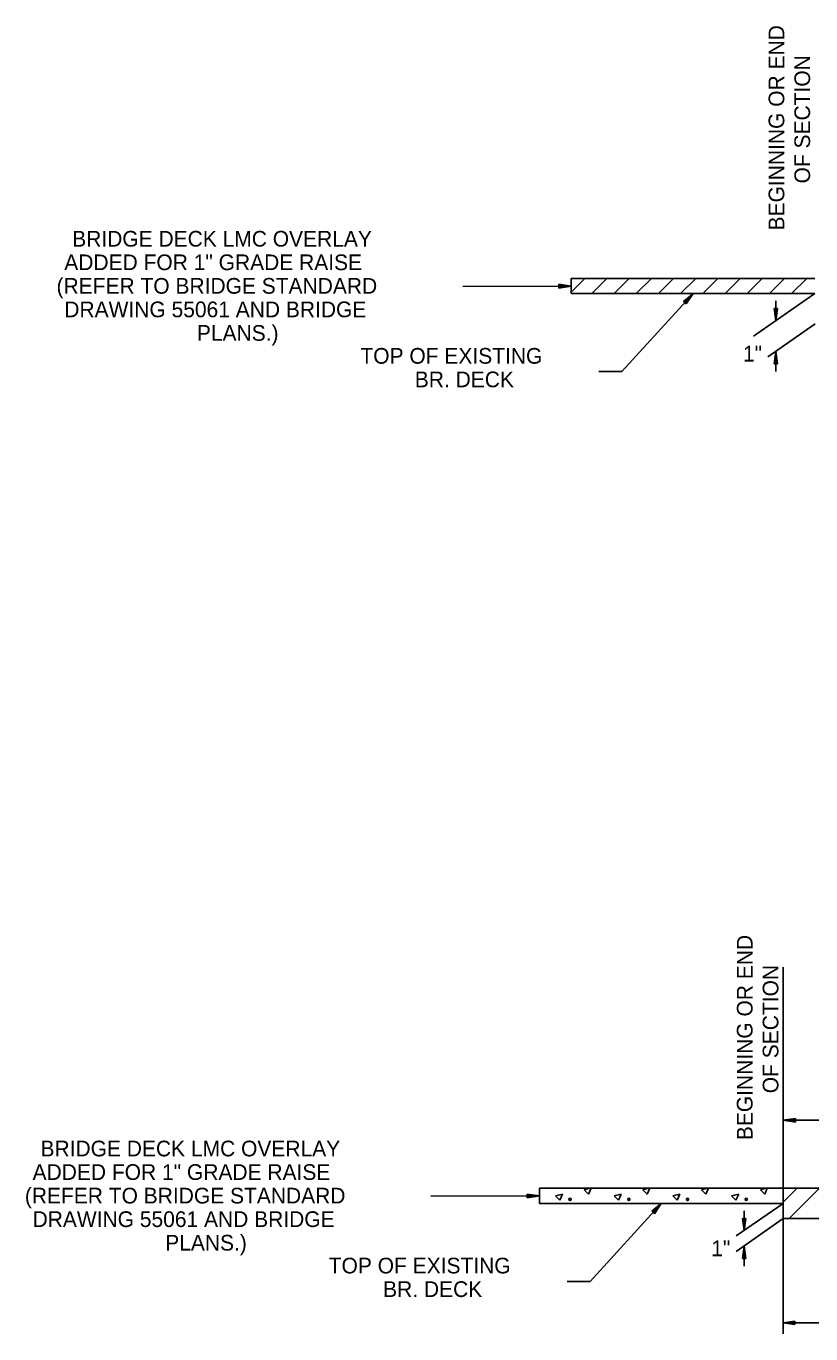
# Model space of a CAD drawing. Extents: x 1929624 to 1935547, y 596315 to 605721.
# Drawn here: x 1931522.3 to 1931822.3, y 602426.5 to 602926.3 of the extents above; entities that cross this region are included whole.
import ezdxf

# ---------------------------------------------------------------- set-up
doc = ezdxf.new("R2010")
doc.units = 0
doc.layers.add('Default', color=7, linetype='Continuous')
doc.layers.add('R_Annotation', color=7, linetype='Continuous')

msp = doc.modelspace()

# ---------------------------------------------------------------- linework, layer by layer
at = {"layer": 'Default'}
for p, q in [((1931689.17, 602826.79), (1931730.62, 602826.95)), ((1931725.91, 602826.22), (1931725.96, 602827.63)), ((1931725.91, 602826.22), (1931730.62, 602826.95)), ((1931725.92, 602827.33), (1931729.03, 602826.88)), ((1931725.96, 602827.63), (1931730.62, 602826.95)), ((1931725.96, 602826.53), (1931727.61, 602826.92)), ((1931725.96, 602826.53), (1931728.22, 602826.83)), ((1931726.01, 602826.84), (1931726.8, 602826.89)), ((1931726.01, 602826.84), (1931726.8, 602826.89)), ((1931726.05, 602827.15), (1931727.61, 602826.92)), ((1931726.05, 602827.15), (1931728.22, 602826.83)), ((1931726.09, 602827.46), (1931729.83, 602826.91)), ((1931726.09, 602826.36), (1931729.83, 602826.91)), ((1931726.09, 602826.36), (1931729.03, 602826.88)), ((1931730.62, 602824.06), (1931823.87, 602824.07)), ((1931750.04, 602794.26), (1931777.25, 602824.07)), ((1931773.59, 602821.1), (1931777.25, 602824.07)), ((1931774.59, 602820.11), (1931773.59, 602821.1)), ((1931773.78, 602820.86), (1931776.22, 602822.84)), ((1931773.8, 602821.08), (1931776.74, 602823.46)), ((1931774.01, 602820.84), (1931775.7, 602822.21)), ((1931774.01, 602820.84), (1931775.23, 602821.83)), ((1931774.21, 602820.6), (1931774.7, 602821.21)), ((1931774.21, 602820.6), (1931774.7, 602821.21)), ((1931774.4, 602820.36), (1931775.7, 602822.21)), ((1931774.4, 602820.36), (1931775.23, 602821.83)), ((1931774.59, 602820.11), (1931777.25, 602824.07)), ((1931774.61, 602820.33), (1931776.74, 602823.46)), ((1931774.61, 602820.33), (1931776.22, 602822.84)), ((1931800.32, 602807.77), (1931823.87, 602824.07)), ((1931808.93, 602813.69), (1931808.93, 602821.27)), ((1931808.27, 602818.35), (1931808.93, 602813.69)), ((1931809.6, 602818.35), (1931808.27, 602818.35)), ((1931808.49, 602818.35), (1931808.93, 602815.25)), ((1931808.49, 602818.35), (1931808.93, 602814.59)), ((1931808.7, 602818.35), (1931808.93, 602816.81)), ((1931808.7, 602818.35), (1931808.93, 602816.14)), ((1931809.6, 602818.35), (1931808.93, 602813.69)), ((1931809.15, 602818.35), (1931808.93, 602816.81)), ((1931809.38, 602818.35), (1931808.93, 602815.25)), ((1931809.6, 602818.35), (1931808.93, 602814.59)), ((1931809.38, 602818.35), (1931808.93, 602816.14)), ((1931808.93, 602818.35), (1931808.93, 602817.69)), ((1931809.15, 602818.35), (1931808.93, 602817.69)), ((1931805.89, 602799.86), (1931823.88, 602812.53)), ((1931808.25, 602797.23), (1931808.91, 602801.9)), ((1931808.48, 602797.23), (1931808.91, 602801.23)), ((1931808.48, 602797.23), (1931808.91, 602800.34)), ((1931808.68, 602797.23), (1931808.91, 602799.67)), ((1931809.58, 602797.23), (1931808.91, 602801.9)), ((1931808.91, 602794.35), (1931808.91, 602801.9)), ((1931809.58, 602797.23), (1931808.91, 602801.23)), ((1931809.36, 602797.23), (1931808.91, 602800.34)), ((1931809.36, 602797.23), (1931808.91, 602799.67)), ((1931750.04, 602794.26), (1931741.27, 602794.26)), ((1931808.25, 602797.23), (1931809.58, 602797.23)), ((1931808.68, 602797.23), (1931808.91, 602798.78)), ((1931809.13, 602797.23), (1931808.91, 602798.78)), ((1931809.13, 602797.23), (1931808.91, 602798.13)), ((1931808.91, 602797.23), (1931808.91, 602798.13)), ((1931811.75, 602482.14), (1931811.75, 602566.66)), ((1931816.41, 602508.8), (1931811.75, 602508.13)), ((1931811.75, 602508.13), (1932223.07, 602508.13)), ((1931816.41, 602507.47), (1931811.75, 602508.13)), ((1931816.41, 602508.58), (1931812.42, 602508.13)), ((1931816.41, 602507.47), (1931812.42, 602508.13)), ((1931816.41, 602508.58), (1931813.31, 602508.13)), ((1931816.41, 602507.69), (1931813.31, 602508.13)), ((1931816.41, 602508.35), (1931814.2, 602508.13)), ((1931816.41, 602507.69), (1931814.2, 602508.13)), ((1931816.41, 602508.35), (1931814.87, 602508.13)), ((1931816.41, 602507.92), (1931814.87, 602508.13)), ((1931816.41, 602508.13), (1931815.75, 602508.13)), ((1931816.41, 602507.92), (1931815.75, 602508.13)), ((1931816.41, 602507.47), (1931816.41, 602508.8)), ((1931713.78, 602478.53), (1931713.83, 602479.94)), ((1931713.79, 602479.64), (1931716.9, 602479.18)), ((1931713.83, 602479.94), (1931718.5, 602479.25)), ((1931713.93, 602479.45), (1931715.48, 602479.22)), ((1931713.93, 602479.45), (1931716.09, 602479.13)), ((1931713.96, 602479.77), (1931717.7, 602479.22)), ((1931677.04, 602479.1), (1931718.5, 602479.25)), ((1931713.78, 602478.53), (1931718.5, 602479.25)), ((1931713.84, 602478.84), (1931715.48, 602479.22)), ((1931713.84, 602478.84), (1931716.09, 602479.13)), ((1931713.89, 602479.14), (1931714.67, 602479.19)), ((1931713.89, 602479.14), (1931714.67, 602479.19)), ((1931713.97, 602478.67), (1931717.7, 602479.22)), ((1931713.97, 602478.67), (1931716.9, 602479.18)), ((1931718.5, 602476.37), (1931811.75, 602476.38)), ((1931737.92, 602446.57), (1931765.12, 602476.37)), ((1931761.46, 602473.4), (1931765.12, 602476.37)), ((1931761.65, 602473.17), (1931764.09, 602475.15)), ((1931761.67, 602473.38), (1931764.61, 602475.76)), ((1931761.88, 602473.14), (1931763.58, 602474.52)), ((1931762.27, 602472.66), (1931763.58, 602474.52)), ((1931762.46, 602472.41), (1931765.12, 602476.37)), ((1931762.49, 602472.64), (1931764.61, 602475.76)), ((1931762.49, 602472.64), (1931764.09, 602475.15)), ((1931793.76, 602463.93), (1931811.75, 602476.38)), ((1931811.75, 602426.51), (1931811.75, 602476.38)), ((1931762.46, 602472.41), (1931761.46, 602473.4)), ((1931761.88, 602473.14), (1931763.1, 602474.13)), ((1931762.08, 602472.9), (1931762.58, 602473.51)), ((1931762.08, 602472.9), (1931762.58, 602473.51)), ((1931762.27, 602472.66), (1931763.1, 602474.13)), ((1931793.76, 602457.93), (1931811.75, 602470.6)), ((1931796.14, 602470.66), (1931796.8, 602465.99)), ((1931797.47, 602470.66), (1931796.14, 602470.66)), ((1931796.37, 602470.66), (1931796.8, 602467.55)), ((1931796.37, 602470.66), (1931796.8, 602466.89)), ((1931796.57, 602470.66), (1931796.8, 602469.11)), ((1931796.57, 602470.66), (1931796.8, 602468.44)), ((1931796.8, 602465.99), (1931796.8, 602473.57)), ((1931797.47, 602470.66), (1931796.8, 602465.99)), ((1931797.02, 602470.66), (1931796.8, 602469.11)), ((1931797.25, 602470.66), (1931796.8, 602467.55)), ((1931797.47, 602470.66), (1931796.8, 602466.89)), ((1931797.25, 602470.66), (1931796.8, 602468.44)), ((1931796.8, 602470.66), (1931796.8, 602469.99)), ((1931797.02, 602470.66), (1931796.8, 602469.99)), ((1931796.12, 602455.31), (1931796.78, 602459.98)), ((1931797.45, 602455.31), (1931796.78, 602459.98)), ((1931796.78, 602452.42), (1931796.78, 602459.98)), ((1931796.12, 602455.31), (1931797.45, 602455.31)), ((1931796.35, 602455.31), (1931796.78, 602459.31)), ((1931796.35, 602455.31), (1931796.78, 602458.41)), ((1931796.55, 602455.31), (1931796.78, 602457.75)), ((1931796.55, 602455.31), (1931796.78, 602456.85)), ((1931797.45, 602455.31), (1931796.78, 602459.31)), ((1931797.23, 602455.31), (1931796.78, 602458.41)), ((1931797.23, 602455.31), (1931796.78, 602457.75)), ((1931797, 602455.31), (1931796.78, 602456.85)), ((1931797, 602455.31), (1931796.78, 602456.2)), ((1931796.78, 602455.31), (1931796.78, 602456.2)), ((1931737.92, 602446.57), (1931729.14, 602446.57)), ((1931816.21, 602431.36), (1931811.75, 602430.71)), ((1932223.07, 602430.71), (1931811.75, 602430.71)), ((1931816.21, 602430.04), (1931811.75, 602430.71)), ((1931816.21, 602431.36), (1931812.42, 602430.71)), ((1931816.21, 602430.26), (1931812.42, 602430.71)), ((1931816.21, 602431.16), (1931813.31, 602430.71)), ((1931816.21, 602430.26), (1931813.31, 602430.71)), ((1931816.21, 602431.16), (1931813.97, 602430.71)), ((1931816.21, 602430.48), (1931813.97, 602430.71)), ((1931816.21, 602430.92), (1931814.87, 602430.71)), ((1931816.21, 602430.48), (1931814.87, 602430.71)), ((1931816.21, 602430.92), (1931815.53, 602430.71)), ((1931816.21, 602430.71), (1931815.53, 602430.71)), ((1931816.21, 602430.04), (1931816.21, 602431.36))]:
    msp.add_line(p, q, dxfattribs=at)
msp.add_lwpolyline([(1931811.75, 602476.38), (1931811.75, 602476.38)], dxfattribs=at)
at = {"layer": 'R_Annotation'}
for p, q in [((1931810.01, 602829.84), (1931730.62, 602829.83)), ((1931730.62, 602829.83), (1931730.62, 602824.06)), ((1931730.62, 602824.61), (1931735.85, 602829.83)), ((1931738.56, 602824.06), (1931744.33, 602829.83)), ((1931747.05, 602824.06), (1931752.82, 602829.83)), ((1931755.54, 602824.06), (1931761.31, 602829.83)), ((1931764.02, 602824.07), (1931769.79, 602829.84)), ((1931772.51, 602824.07), (1931778.28, 602829.84)), ((1931780.99, 602824.07), (1931786.76, 602829.84)), ((1931789.48, 602824.07), (1931795.25, 602829.84)), ((1931797.97, 602824.07), (1931803.74, 602829.84)), ((1931806.45, 602824.07), (1931812.22, 602829.84)), ((1931823.87, 602829.84), (1931810.01, 602829.84)), ((1931814.94, 602824.07), (1931820.7, 602829.84)), ((1931797.88, 602482.14), (1931718.5, 602482.14)), ((1931718.5, 602482.14), (1931718.5, 602476.37)), ((1931724.64, 602479.21), (1931727.34, 602479.95)), ((1931727.34, 602479.95), (1931726.3, 602477.57)), ((1931735.62, 602481.59), (1931737.62, 602482.14)), ((1931737.28, 602479.95), (1931735.62, 602481.59)), ((1931738.25, 602482.14), (1931737.28, 602479.95)), ((1931747.1, 602479.21), (1931749.8, 602479.95)), ((1931749.8, 602479.95), (1931748.76, 602477.57)), ((1931758.07, 602481.59), (1931760.09, 602482.14)), ((1931759.73, 602479.95), (1931758.07, 602481.59)), ((1931760.7, 602482.14), (1931759.73, 602479.95)), ((1931769.55, 602479.21), (1931772.25, 602479.95)), ((1931772.25, 602479.95), (1931771.21, 602477.57)), ((1931780.52, 602481.59), (1931782.55, 602482.14)), ((1931782.18, 602479.95), (1931780.52, 602481.59)), ((1931783.16, 602482.14), (1931782.18, 602479.95)), ((1931792, 602479.21), (1931794.7, 602479.95)), ((1931794.7, 602479.95), (1931793.66, 602477.57)), ((1931811.75, 602482.14), (1931797.88, 602482.14)), ((1931802.98, 602481.59), (1931805, 602482.14)), ((1931804.64, 602479.95), (1931802.98, 602481.59)), ((1931805.61, 602482.14), (1931804.64, 602479.95)), ((1932223.08, 602482.18), (1931811.75, 602482.14)), ((1932223.08, 602482.18), (1931811.75, 602482.14)), ((1931811.75, 602476.83), (1931817.06, 602482.14)), ((1931811.75, 602476.38), (1931811.75, 602482.14)), ((1931814.01, 602470.6), (1931825.55, 602482.14)), ((1931726.3, 602477.57), (1931724.64, 602479.21)), ((1931748.76, 602477.57), (1931747.1, 602479.21)), ((1931771.21, 602477.57), (1931769.55, 602479.21)), ((1931793.66, 602477.57), (1931792, 602479.21)), ((1931811.75, 602476.38), (1931811.75, 602470.6)), ((1931811.75, 602476.38), (1931811.75, 602470.61)), ((1931811.75, 602470.6), (1932223.09, 602470.64))]:
    msp.add_line(p, q, dxfattribs=at)
for points in [[(1931730.62, 602824.06), (1931823.87, 602824.07)], [(1931718.5, 602476.37), (1931811.75, 602476.38)]]:
    msp.add_lwpolyline(points, dxfattribs=at)
for centre in [(1931730.23, 602477.9), (1931730.23, 602477.9), (1931752.69, 602477.9), (1931752.69, 602477.9), (1931775.14, 602477.9), (1931775.14, 602477.9), (1931797.59, 602477.9), (1931797.59, 602477.9)]:
    msp.add_ellipse(centre, major_axis=(0, 0.411), ratio=0.9997, dxfattribs=at)

# ---------------------------------------------------------------- texts
at = {"layer": 'Default'}
for s, rotation, p in [('BEGINNING OR END', 90, (1931812.14, 602848.22)), ('OF SECTION', 90, (1931822, 602866.17)), ('BRIDGE DECK LMC OVERLAY ', 360, (1931539.88, 602842.04)), ('ADDED FOR 1" GRADE RAISE', 360, (1931536.85, 602833.04)), ('(REFER TO BRIDGE STANDARD', 360, (1931533.9, 602824.04)), ('DRAWING 55061 AND BRIDGE', 360, (1931536.86, 602815.04)), (' PLANS.)', 360, (1931585.33, 602806.04)), ('TOP OF EXISTING ', 360, (1931650.08, 602797.29)), ('1"', 360, (1931796.33, 602798.13)), ('BR. DECK', 360, (1931670.87, 602788.29)), ('BEGINNING OR END', 90, (1931800.01, 602500.53)), ('OF SECTION', 90, (1931809.88, 602518.47)), ('BRIDGE DECK LMC OVERLAY ', 360, (1931527.76, 602494.34)), ('ADDED FOR 1" GRADE RAISE', 360, (1931524.73, 602485.34)), ('(REFER TO BRIDGE STANDARD', 360, (1931521.77, 602476.34)), ('DRAWING 55061 AND BRIDGE', 360, (1931524.73, 602467.34)), (' PLANS.)', 360, (1931573.21, 602458.34)), ('1"', 360, (1931784.2, 602456.2)), ('TOP OF EXISTING ', 360, (1931637.96, 602449.6)), ('BR. DECK', 360, (1931658.75, 602440.6))]:
    msp.add_text(s, height=6, rotation=rotation, dxfattribs=at).set_placement(p)

doc.saveas('drawing.dxf')
